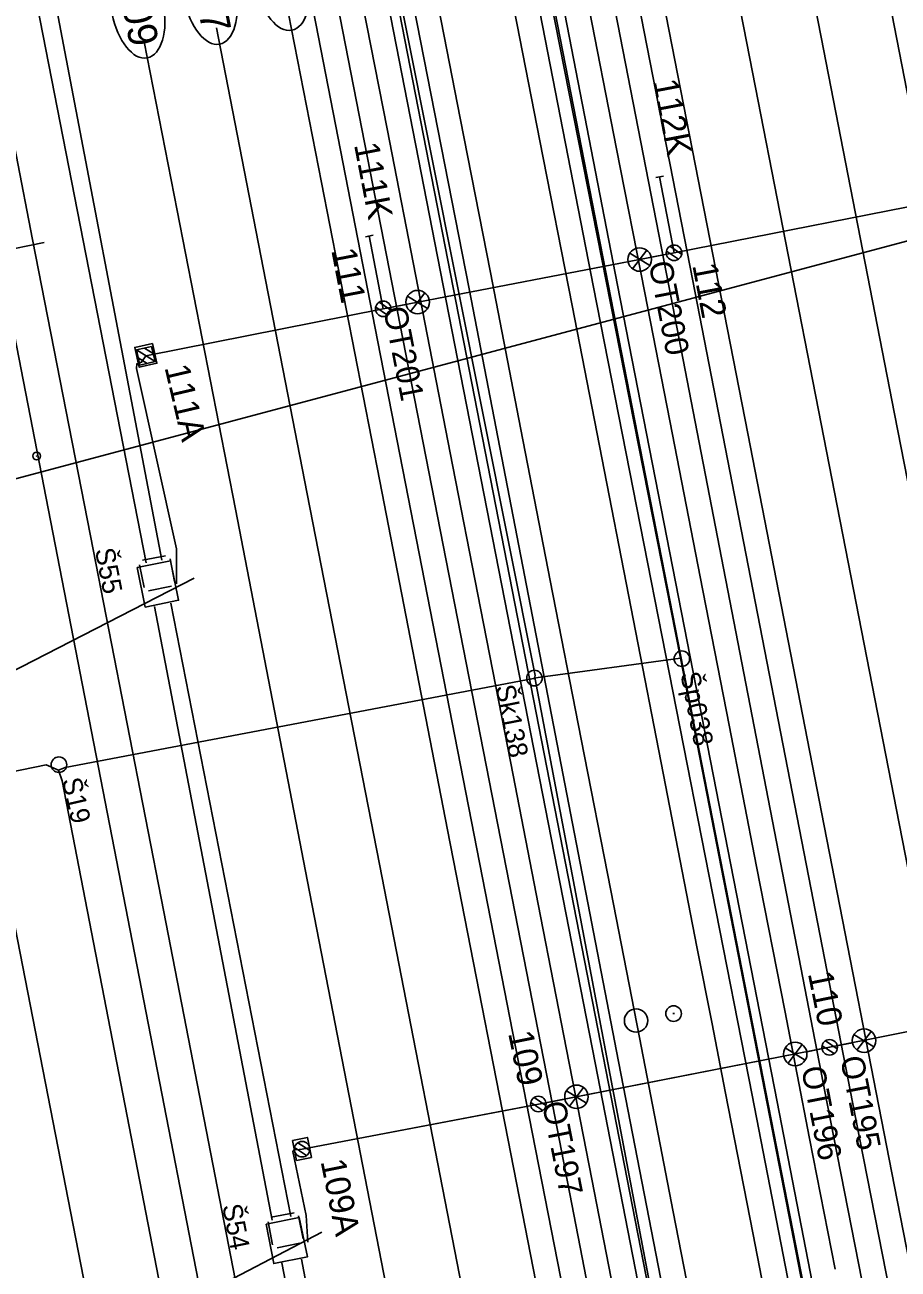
# Model space of a CAD drawing. Extents: x -545846 to -545044, y -1122650 to -1119108.
# Drawn here: x -545569.2 to -545513, y -1120179.3 to -1120099.3 of the extents above; entities that cross this region are included whole.
import ezdxf

# ---------------------------------------------------------------- set-up
doc = ezdxf.new("R2010")
doc.units = 0
for name, color, linetype in [('osvětlené plochy-hodnota-obrys', 7, 'Continuous'), ('Vrstva 1', 7, 'Continuous'), ('Vrstva 1 - Koleje', 7, 'Continuous'), ('Vrstva 11', 7, 'Continuous'), ('Vrstva 11 - Trakce', 7, 'Continuous'), ('Vrstva 12 - Trakce zaklady', 7, 'Continuous'), ('Vrstva 19 - Staniceni', 7, 'Continuous'), ('Vrstva 2', 7, 'Continuous'), ('Vrstva 25', 7, 'Continuous'), ('Vrstva 26', 7, 'Continuous'), ('Vrstva 28', 7, 'Continuous'), ('Vrstva 34', 7, 'Continuous'), ('Vrstva 35', 7, 'Continuous'), ('Vrstva 36', 7, 'Continuous'), ('Vrstva 4 - Teren - stezky - prechody - plochy', 7, 'Continuous'), ('Vrstva 43', 7, 'Continuous'), ('Vrstva 44', 7, 'Continuous'), ('Vrstva 63', 7, 'Continuous'), ('Vrstva 7 - Namezniky-vystroj', 7, 'Continuous')]:
    doc.layers.add(name, color=color, linetype=linetype)

msp = doc.modelspace()

# ---------------------------------------------------------------- linework, layer by layer
at = {"layer": 'osvětlené plochy-hodnota-obrys'}
for points in [[(-545607.519, -1119727.517), (-545482.536, -1120367.871), (-545465.73, -1120446.743)], [(-545611.105, -1119760.367), (-545492.389, -1120368.615), (-545475.582, -1120447.487)], [(-545605.8, -1119934.355), (-545489.142, -1120534.587)]]:
    msp.add_lwpolyline(points, dxfattribs=at)
at = {"layer": 'Vrstva 1'}
for points in [[(-545514.869, -1120091.287), (-545513.451, -1120098.557), (-545508.6, -1120123.411), (-545503.814, -1120147.933), (-545499.189, -1120171.635), (-545495.289, -1120191.685)], [(-545519.535, -1120092.195), (-545517.996, -1120100.078), (-545513.27, -1120124.289), (-545508.484, -1120148.785), (-545503.877, -1120172.488), (-545499.955, -1120192.584)], [(-545524.202, -1120093.104), (-545522.572, -1120101.445), (-545517.985, -1120124.938), (-545513.148, -1120149.737), (-545508.594, -1120173.088), (-545507.977, -1120176.235)], [(-545528.882, -1120094.015), (-545528.162, -1120097.704), (-545522.715, -1120125.548), (-545517.799, -1120150.761), (-545513.279, -1120173.946), (-545509.639, -1120192.576)], [(-545552.238, -1120098.563), (-545550.124, -1120109.416), (-545546.372, -1120128.612), (-545542.01, -1120151.03), (-545537.015, -1120176.573), (-545532.964, -1120197.345)], [(-545556.874, -1120099.465), (-545554.636, -1120110.932), (-545551.032, -1120129.425), (-545546.39, -1120153.243), (-545540.625, -1120182.853), (-545537.673, -1120197.983)], [(-545561.526, -1120100.371), (-545559.408, -1120111.222), (-545555.658, -1120130.417), (-545551.013, -1120154.339), (-545545.825, -1120181.022), (-545542.287, -1120199.17)], [(-545570.823, -1120102.181), (-545568.694, -1120113.076), (-545564.977, -1120132.12), (-545560.258, -1120156.304), (-545555.087, -1120182.9), (-545551.543, -1120201.059)], [(-545580.19, -1120104.005), (-545578.009, -1120115.24), (-545574.338, -1120134.054), (-545570.635, -1120153.121), (-545564.446, -1120184.79), (-545559.991, -1120207.618)]]:
    msp.add_lwpolyline(points, dxfattribs=at)
for centre in [(-545552.642, -1120096.479), (-545557.281, -1120097.365), (-545561.936, -1120098.253)]:
    msp.add_ellipse(centre, major_axis=(0.614, -3.151), ratio=0.521067, dxfattribs=at)
at = {"layer": 'Vrstva 1 - Koleje'}
for points in [[(-545565.242, -1120006.761), (-545563.215, -1120017.132), (-545561.328, -1120026.813), (-545559.685, -1120035.275), (-545557.783, -1120045.016), (-545555.954, -1120054.415), (-545553.446, -1120067.277), (-545551.651, -1120076.487), (-545549.618, -1120086.89), (-545547.731, -1120096.57), (-545545.899, -1120105.967), (-545543.904, -1120116.213), (-545541.838, -1120126.795), (-545539.892, -1120136.779), (-545537.95, -1120146.749), (-545536.037, -1120156.578), (-545534.37, -1120165.141), (-545532.743, -1120173.486), (-545531.198, -1120181.414)], [(-545560.08, -1120008.438), (-545558.344, -1120017.351), (-545556.681, -1120025.905), (-545554.861, -1120035.223), (-545552.908, -1120045.228), (-545550.866, -1120055.726), (-545548.758, -1120066.525), (-545547.531, -1120072.803), (-545545.346, -1120084.006), (-545543.28, -1120094.6), (-545541.202, -1120105.269), (-545539.263, -1120115.208), (-545537.306, -1120125.3), (-545535.418, -1120134.997), (-545533.428, -1120145.199), (-545531.528, -1120154.933), (-545529.681, -1120164.388), (-545527.503, -1120175.582), (-545525.637, -1120185.143)], [(-545550.091, -1120010.035), (-545548.279, -1120019.346), (-545546.438, -1120028.776), (-545544.775, -1120037.331), (-545543.051, -1120046.156), (-545541.321, -1120055.024), (-545539.415, -1120064.806), (-545538.667, -1120068.636), (-545536.912, -1120077.658), (-545534.963, -1120087.664), (-545533.054, -1120097.451), (-545531.143, -1120107.252), (-545529.333, -1120116.507), (-545527.563, -1120125.605), (-545525.777, -1120134.768), (-545523.919, -1120144.304), (-545522.147, -1120153.393), (-545520.336, -1120162.648), (-545518.735, -1120170.873), (-545517.092, -1120179.279)], [(-545554.789, -1120010.755), (-545552.734, -1120021.311), (-545550.891, -1120030.759), (-545548.821, -1120041.368), (-545546.871, -1120051.376), (-545545.13, -1120060.312), (-545544.093, -1120065.626), (-545542.082, -1120075.939), (-545540.1, -1120086.083), (-545538.091, -1120096.401), (-545536.08, -1120106.734), (-545534.011, -1120117.331), (-545532.253, -1120126.344), (-545530.211, -1120136.809), (-545528.001, -1120148.161), (-545525.979, -1120158.546), (-545525.011, -1120163.503), (-545524.168, -1120167.854), (-545522.376, -1120177.035), (-545520.607, -1120186.115)]]:
    msp.add_lwpolyline(points, dxfattribs=at)
at = {"layer": 'Vrstva 11'}
msp.add_lwpolyline([(-545595.323, -1120119.067), (-545570.901, -1120113.867), (-545567.941, -1120113.275)], dxfattribs=at)
at = {"layer": 'Vrstva 11 - Trakce'}
for p, q in [((-545528.133, -1120109.001), (-545528.625, -1120109.094)), ((-545527.453, -1120113.934), (-545528.382, -1120109.048)), ((-545546.805, -1120112.803), (-545547.296, -1120112.898)), ((-545547.053, -1120112.851), (-545546.152, -1120117.533)), ((-545527.937, -1120113.821), (-545527.171, -1120114.342)), ((-545527.72, -1120113.515), (-545526.965, -1120114.029)), ((-545546.42, -1120117.115), (-545545.663, -1120117.627)), ((-545546.636, -1120117.421), (-545545.869, -1120117.941)), ((-545562.019, -1120120.174), (-545560.821, -1120120.918)), ((-545561.503, -1120120.054), (-545560.942, -1120120.402)), ((-545561.902, -1120120.688), (-545561.333, -1120121.041)), ((-545517.936, -1120164.903), (-545517.164, -1120165.415)), ((-545517.723, -1120164.595), (-545516.961, -1120165.099)), ((-545536.449, -1120168.241), (-545535.687, -1120168.745)), ((-545536.662, -1120168.549), (-545535.89, -1120169.061)), ((-545551.848, -1120171.452), (-545551.076, -1120171.964)), ((-545551.635, -1120171.144), (-545550.873, -1120171.648))]:
    msp.add_line(p, q, dxfattribs=at)
for points in [[(-545561.421, -1120120.548), (-545546.152, -1120117.533), (-545527.453, -1120113.934), (-545508.69, -1120110.254), (-545483.996, -1120105.486)], [(-545551.363, -1120171.559), (-545536.177, -1120168.656), (-545517.451, -1120165.01), (-545498.706, -1120161.263), (-545474.043, -1120156.569)]]:
    msp.add_lwpolyline(points, dxfattribs=at)
msp.add_lwpolyline([(-545561.048, -1120119.947), (-545560.82, -1120120.921), (-545561.794, -1120121.149), (-545562.022, -1120120.175)], close=True, dxfattribs=at)
for centre in [(-545527.453, -1120113.934), (-545546.152, -1120117.533), (-545517.451, -1120165.01), (-545536.177, -1120168.656), (-545551.363, -1120171.559)]:
    msp.add_circle(centre, 0.5, dxfattribs=at)
at = {"layer": 'Vrstva 12 - Trakce zaklady'}
for p, q in [((-545562.13, -1120120.012), (-545560.991, -1120119.773)), ((-545560.702, -1120121.037), (-545561.832, -1120121.285))]:
    msp.add_line(p, q, dxfattribs=at)
for points in [[(-545562.13, -1120120.012), (-545560.991, -1120119.773), (-545560.702, -1120121.037), (-545561.832, -1120121.285), (-545562.13, -1120120.012)], [(-545562.13, -1120120.012), (-545562.13, -1120120.012), (-545561.832, -1120121.285), (-545561.832, -1120121.285)], [(-545560.991, -1120119.773), (-545560.991, -1120119.773), (-545560.702, -1120121.037), (-545560.702, -1120121.037)], [(-545551.981, -1120170.999), (-545551.03, -1120170.806), (-545550.77, -1120172.089), (-545551.721, -1120172.281), (-545551.981, -1120170.999)]]:
    msp.add_lwpolyline(points, dxfattribs=at)
at = {"layer": 'Vrstva 19 - Staniceni'}
msp.add_circle((-545529.896, -1120163.288), 0.75, dxfattribs=at)
at = {"layer": 'Vrstva 25'}
for p, q in [((-545530.124, -1120114.962), (-545529.212, -1120113.762)), ((-545528.925, -1120114.222), (-545527.453, -1120113.934)), ((-545530.303, -1120113.963), (-545529.02, -1120114.754)), ((-545543.301, -1120117.505), (-545544.585, -1120116.714)), ((-545543.48, -1120116.506), (-545544.393, -1120117.705)), ((-545544.68, -1120117.246), (-545546.152, -1120117.533)), ((-545514.6, -1120164.983), (-545515.884, -1120164.191)), ((-545514.779, -1120163.984), (-545515.692, -1120165.183)), ((-545520.302, -1120165.037), (-545519.018, -1120165.829)), ((-545520.123, -1120166.036), (-545519.21, -1120164.837)), ((-545518.923, -1120165.297), (-545517.451, -1120165.01)), ((-545515.979, -1120164.723), (-545517.451, -1120165.01)), ((-545533.089, -1120168.593), (-545534.373, -1120167.801)), ((-545533.268, -1120167.594), (-545534.181, -1120168.793)), ((-545534.468, -1120168.333), (-545535.94, -1120168.62))]:
    msp.add_line(p, q, dxfattribs=at)
for points in [[(-545561.421, -1120120.548), (-545546.152, -1120117.533), (-545527.453, -1120113.934)], [(-545551.363, -1120171.559), (-545535.94, -1120168.62), (-545517.451, -1120165.01)]]:
    msp.add_lwpolyline(points, dxfattribs=at)
for centre in [(-545529.666, -1120114.364), (-545543.939, -1120117.104), (-545515.238, -1120164.581), (-545519.664, -1120165.439), (-545533.727, -1120168.191)]:
    msp.add_circle(centre, 0.754, dxfattribs=at)
at = {"layer": 'Vrstva 26'}
for points in [[(-545561.421, -1120120.548), (-545561.689, -1120120.963), (-545561.992, -1120121.061), (-545562.022, -1120121.381), (-545559.451, -1120132.972), (-545559.442, -1120135.211)], [(-545550.999, -1120177.538), (-545551.107, -1120175.825), (-545551.959, -1120171.71), (-545551.868, -1120171.602), (-545551.548, -1120171.579), (-545551.363, -1120171.559)]]:
    msp.add_lwpolyline(points, dxfattribs=at)
at = {"layer": 'Vrstva 28'}
msp.add_line((-545568.425, -1120127.018), (-545568.435, -1120126.968), dxfattribs=at)
msp.add_circle((-545568.43, -1120126.993), 0.25, dxfattribs=at)
at = {"layer": 'Vrstva 34'}
for p, q in [((-545561.618, -1120133.693), (-545560.146, -1120133.405)), ((-545559.853, -1120133.602), (-545559.565, -1120135.074)), ((-545561.527, -1120135.458), (-545561.815, -1120133.986)), ((-545559.762, -1120135.367), (-545561.234, -1120135.655)), ((-545553.267, -1120177.698), (-545553.555, -1120176.226)), ((-545553.358, -1120175.933), (-545551.886, -1120175.645)), ((-545551.593, -1120175.842), (-545551.305, -1120177.314)), ((-545551.502, -1120177.607), (-545552.974, -1120177.895))]:
    msp.add_line(p, q, dxfattribs=at)
at = {"layer": 'Vrstva 35'}
for points in [[(-545561.385, -1120133.863), (-545569.121, -1120094.259)], [(-545560.376, -1120133.685), (-545567.955, -1120094.019)], [(-545553.287, -1120176.111), (-545560.86, -1120136.679)], [(-545552.089, -1120175.895), (-545559.81, -1120136.461)], [(-545543.959, -1120217.982), (-545551.408, -1120178.629)], [(-545545.093, -1120218.303), (-545552.679, -1120178.871)]]:
    msp.add_lwpolyline(points, dxfattribs=at)
at = {"layer": 'Vrstva 36'}
for p, q in [((-545561.446, -1120136.706), (-545561.446, -1120136.706)), ((-545553.184, -1120178.914), (-545553.184, -1120178.914))]:
    msp.add_line(p, q, dxfattribs=at)
for points in [[(-545561.966, -1120134.169), (-545559.827, -1120133.733), (-545559.305, -1120136.272), (-545561.446, -1120136.706), (-545561.966, -1120134.169)], [(-545561.966, -1120134.169), (-545559.827, -1120133.733), (-545559.305, -1120136.272), (-545561.446, -1120136.706), (-545561.966, -1120134.169)], [(-545559.827, -1120133.733), (-545559.827, -1120133.733)], [(-545561.966, -1120134.169), (-545561.966, -1120134.169)], [(-545559.305, -1120136.272), (-545559.305, -1120136.272)], [(-545553.667, -1120176.388), (-545551.557, -1120175.954), (-545551.023, -1120178.482), (-545553.184, -1120178.914), (-545553.667, -1120176.388)], [(-545553.667, -1120176.388), (-545551.557, -1120175.954), (-545551.023, -1120178.482), (-545553.184, -1120178.914), (-545553.667, -1120176.388)], [(-545551.557, -1120175.954), (-545551.557, -1120175.954)], [(-545553.667, -1120176.388), (-545553.667, -1120176.388)], [(-545551.023, -1120178.482), (-545551.023, -1120178.482)]]:
    msp.add_lwpolyline(points, dxfattribs=at)
at = {"layer": 'Vrstva 4 - Teren - stezky - prechody - plochy'}
for points in [[(-545624.215, -1119622.224), (-545623.342, -1119622.007), (-545620.608, -1119632.171), (-545618.464, -1119642.593), (-545609.99, -1119685.9), (-545599.422, -1119740.168), (-545590.883, -1119784.038), (-545582.301, -1119828.162), (-545571.506, -1119883.387), (-545561.049, -1119937.185), (-545548.968, -1119999.368), (-545536.73, -1120062.107), (-545526.255, -1120115.744), (-545515.983, -1120168.544), (-545503.995, -1120229.495), (-545494.446, -1120278.921), (-545489.088, -1120306.388), (-545486.967, -1120316.535), (-545487.846, -1120316.754)], [(-545628.853, -1119622.763), (-545624.686, -1119644.063), (-545616.354, -1119686.873), (-545605.869, -1119740.58), (-545597.619, -1119782.547), (-545588.666, -1119828.365), (-545577.778, -1119884.555), (-545567.555, -1119936.921), (-545555.278, -1120000.024), (-545543.118, -1120062.357), (-545532.633, -1120116.151), (-545522.436, -1120168.075), (-545510.345, -1120230.332), (-545500.633, -1120280.001), (-545495.304, -1120307.199), (-545490.342, -1120331.504), (-545485.9, -1120353.688), (-545480.839, -1120378)], [(-545627.289, -1119622.488), (-545623.041, -1119643.798), (-545614.848, -1119686.378), (-545604.257, -1119740.381), (-545596.077, -1119782.585), (-545587.168, -1119828.353), (-545576.202, -1119884.317), (-545565.971, -1119936.976), (-545553.74, -1119999.834), (-545541.535, -1120062.236), (-545531.079, -1120116.013), (-545520.819, -1120168.515), (-545508.831, -1120230.344), (-545499.12, -1120279.845), (-545497.248, -1120289.164), (-545495.162, -1120299.078), (-545493.408, -1120306.853), (-545489.261, -1120323.659), (-545486.768, -1120332.638), (-545482.019, -1120349.033), (-545479.258, -1120359.037), (-545477.044, -1120368.814), (-545475.362, -1120376.928)], [(-545624.215, -1119622.224), (-545621.684, -1119634.807), (-545620.048, -1119643.216), (-545611.648, -1119686.181), (-545601.152, -1119739.942), (-545592.571, -1119783.992), (-545583.867, -1119828.341), (-545573.059, -1119883.823), (-545562.652, -1119937.218), (-545550.46, -1119999.458), (-545538.284, -1120062.171), (-545527.796, -1120116.054), (-545517.608, -1120168.62), (-545505.551, -1120230.109), (-545495.948, -1120279.349), (-545494.121, -1120288.848), (-545492.075, -1120298.544), (-545490.237, -1120306.578), (-545487.846, -1120316.754)], [(-545488.754, -1120379.549), (-545491.925, -1120363.788), (-545496.278, -1120342.782), (-545500.506, -1120321.731), (-545508.599, -1120280.828), (-545518.82, -1120228.621), (-545531.029, -1120165.923), (-545540.626, -1120116.248), (-545552.245, -1120057.042), (-545557.488, -1120030.03), (-545563.439, -1119999.512), (-545572.128, -1119954.79), (-545581.61, -1119906.246), (-545591.458, -1119855.639), (-545600.962, -1119806.943), (-545610.434, -1119758.233), (-545616.648, -1119726.461), (-545621.696, -1119701.088), (-545622.533, -1119696.196), (-545623.462, -1119696.331)], [(-545490.916, -1120379.972), (-545493.99, -1120364.147), (-545502.163, -1120322.09), (-545510.164, -1120281.035), (-545520.235, -1120229.023), (-545532.517, -1120166.017), (-545542.296, -1120116.028), (-545553.809, -1120057.082), (-545558.932, -1120030.597), (-545564.969, -1119999.794), (-545573.753, -1119955.036), (-545583.127, -1119906.578), (-545593.017, -1119855.856), (-545602.553, -1119806.891), (-545612.123, -1119758.671), (-545618.333, -1119726.047), (-545620.676, -1119713.873), (-545622.612, -1119701.558), (-545623.462, -1119696.331)], [(-545495.535, -1120380.876), (-545498.596, -1120365.093), (-545507.092, -1120321.572), (-545515.017, -1120281.173), (-545524.994, -1120229.535), (-545536.771, -1120169.47), (-545546.676, -1120118.787), (-545557.312, -1120064.079), (-545563.312, -1120033.308), (-545569.884, -1119999.645), (-545578.452, -1119955.82), (-545587.921, -1119907.338), (-545597.812, -1119856.591), (-545607.33, -1119807.681), (-545610.119, -1119793.19), (-545611.535, -1119784.447), (-545612.6, -1119777.287), (-545613.018, -1119774.47), (-545612.047, -1119774.376)], [(-545493.924, -1120380.561), (-545496.951, -1120365.161), (-545505.376, -1120321.611), (-545513.278, -1120281.443), (-545523.478, -1120229.493), (-545535.102, -1120169.56), (-545545.054, -1120118.579), (-545554.55, -1120069.937), (-545561.701, -1120033.181), (-545568.213, -1119999.317), (-545576.806, -1119955.508), (-545586.262, -1119907.136), (-545605.677, -1119807.326), (-545612.047, -1119774.376)]]:
    msp.add_lwpolyline(points, dxfattribs=at)
at = {"layer": 'Vrstva 43'}
for centre in [(-545526.952, -1120140.026), (-545536.427, -1120141.271), (-545567, -1120146.841)]:
    msp.add_circle(centre, 0.5, dxfattribs=at)
at = {"layer": 'Vrstva 44'}
for points in [[(-545546.44, -1120041.151), (-545536.872, -1120090.083), (-545527.028, -1120139.996), (-545536.185, -1120141.236), (-545536.421, -1120141.276), (-545536.499, -1120141.302)], [(-545555.749, -1120043.26), (-545546.419, -1120090.806), (-545536.389, -1120141.112), (-545536.421, -1120141.276)], [(-545629.268, -1120065.402), (-545629.634, -1120087.876), (-545630.039, -1120112.736), (-545629.044, -1120137.319), (-545628.839, -1120137.845), (-545628.579, -1120138.408), (-545605.178, -1120154.045), (-545604.485, -1120154.235), (-545603.868, -1120154.242), (-545567.82, -1120146.847), (-545567.035, -1120147.195), (-545566.786, -1120147.869), (-545557.769, -1120194.412), (-545548.548, -1120241.228), (-545548.384, -1120241.623), (-545548.361, -1120241.936), (-545539.222, -1120288.885), (-545539.174, -1120289.236), (-545530.2, -1120336.386), (-545530.153, -1120336.813), (-545530.009, -1120337.37), (-545520.393, -1120385.741)], [(-545508.45, -1120235.904), (-545517.909, -1120186.903), (-545527.028, -1120139.996)], [(-545536.499, -1120141.302), (-545566.592, -1120147.02), (-545567.035, -1120147.195)], [(-545518.036, -1120237.5), (-545527.43, -1120188.641), (-545536.379, -1120141.339), (-545536.421, -1120141.276)]]:
    msp.add_lwpolyline(points, dxfattribs=at)
at = {"layer": 'Vrstva 63'}
for p, q in [((-545482.238, -1120105.103), (-545606.325, -1120138.21)), ((-545558.301, -1120134.848), (-545625.538, -1120169.29)), ((-545550.095, -1120176.89), (-545600.274, -1120203.02))]:
    msp.add_line(p, q, dxfattribs=at)
at = {"layer": 'Vrstva 7 - Namezniky-vystroj'}
msp.add_line((-545527.533, -1120162.841), (-545527.433, -1120162.841), dxfattribs=at)
msp.add_circle((-545527.483, -1120162.841), 0.5, dxfattribs=at)

# ---------------------------------------------------------------- texts
at = {"layer": 'Vrstva 11 - Trakce'}
for s, rotation, p in [('112K', 280.76544, (-545528.803, -1120102.904)), ('111K', 280.89279, (-545548.032, -1120106.984)), ('111', 280.89279, (-545549.496, -1120113.763)), ('112', 280.76544, (-545526.284, -1120114.73)), ('111A', 283.17528, (-545560.219, -1120121.294)), ('110', 281.46455, (-545518.855, -1120160.265)), ('109', 281.46455, (-545538.124, -1120164.098)), ('109A', 281.46455, (-545550.184, -1120172.34))]:
    msp.add_text(s, height=1.6, rotation=rotation, dxfattribs=at).set_placement(p)
at = {"layer": 'Vrstva 2'}
for s, p in [('207', (-545558.541, -1120095.78)), ('209', (-545563.197, -1120096.668))]:
    msp.add_text(s, height=1.875, rotation=280.91172, dxfattribs=at).set_placement(p)
at = {"layer": 'Vrstva 25'}
for s, rotation, p in [('OT200', 281.00927, (-545529.091, -1120114.605)), ('OT201', 281.0473, (-545546.152, -1120117.533)), ('OT195', 281.01491, (-545516.777, -1120165.703)), ('OT196', 281.01491, (-545519.284, -1120166.358)), ('OT197', 281.03239, (-545535.94, -1120168.62))]:
    msp.add_text(s, height=1.5, rotation=rotation, dxfattribs=at).set_placement(p)
at = {"layer": 'Vrstva 34'}
for s, rotation, p in [('Š55', 281.01281, (-545564.693, -1120133.024)), ('Š54', 281.06885, (-545556.511, -1120175.193))]:
    msp.add_text(s, height=1.25, rotation=rotation, dxfattribs=at).set_placement(p)
at = {"layer": 'Vrstva 43'}
for s, rotation, p in [('Šp038', 280.99979, (-545527.053, -1120140.979)), ('Šk138', 280.99979, (-545538.936, -1120141.815)), ('Š19', 282.98932, (-545566.819, -1120147.818))]:
    msp.add_text(s, height=1.25, rotation=rotation, dxfattribs=at).set_placement(p)

doc.saveas('drawing.dxf')
